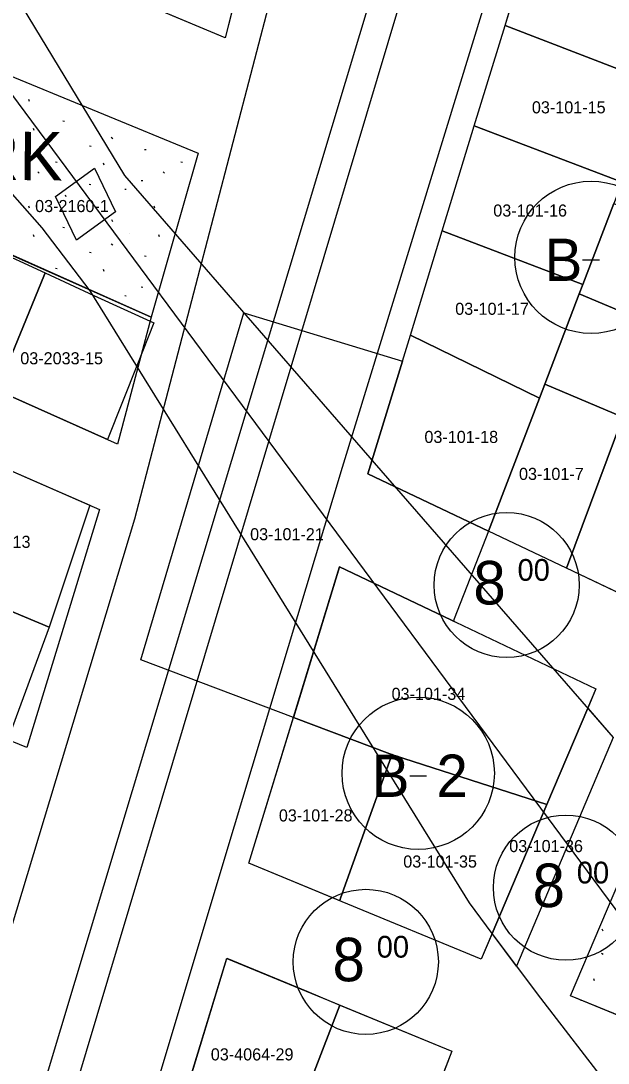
# Model space of a CAD drawing. Extents: x 413946 to 415528, y 4453939 to 4454944.
# Drawn here: x 414280.9 to 414329.5, y 4454485.6 to 4454571.8 of the extents above; entities that cross this region are included whole.
import ezdxf

# ---------------------------------------------------------------- set-up
doc = ezdxf.new("R2010")
doc.units = 0
for name, color, linetype in [('0_KADASTRO', 7, 'Continuous'), ('HAT_ENERJI_NAKIL_HAT', 7, 'Continuous'), ('KST_ENERJI_NAKIL_HAT', 7, 'Continuous'), ('Level 27', 7, 'Continuous'), ('Level 28', 7, 'Continuous'), ('Level 33', 7, 'Continuous'), ('Level 41', 7, 'Continuous'), ('Level 54', 7, 'Continuous'), ('Level 62', 7, 'Continuous'), ('SEMBOL', 7, 'Continuous'), ('SNR_FONKSIYON', 7, 'Continuous')]:
    doc.layers.add(name, color=color, linetype=linetype)

msp = doc.modelspace()

# ---------------------------------------------------------------- linework, layer by layer
at = {"layer": '0_KADASTRO'}
for points in [[(414286.69, 4454575.03), (414291.62, 4454587.04), (414300.98, 4454583.13), (414297.78, 4454570.38)], [(414320.92, 4454571.39), (414322.76, 4454577.41), (414331.26, 4454579.45), (414337.788, 4454577.207), (414333.68, 4454566.5)], [(414318.38, 4454563.09), (414320.92, 4454571.39), (414333.68, 4454566.5), (414332.781, 4454564.135), (414330.6, 4454558.43)], [(414315.73, 4454554.42), (414318.38, 4454563.09), (414330.6, 4454558.43), (414329.929, 4454556.663), (414327.36, 4454549.97)], [(414283.74, 4454557.25), (414286.97, 4454559.61), (414288.7, 4454556), (414285.46, 4454553.65)], [(414327.067, 4454549.19), (414327.36, 4454549.97), (414329.929, 4454556.663), (414343.614, 4454550.92), (414340.572, 4454543.529)], [(414269.78, 4454545.14), (414273.74, 4454555.12), (414282.87, 4454550.93), (414282.76, 4454550.67), (414278.88, 4454541.23)], [(414313.09, 4454545.79), (414315.73, 4454554.42), (414327.36, 4454549.97), (414327.067, 4454549.19), (414324.214, 4454541.717), (414323.77, 4454540.57)], [(414278.88, 4454541.23), (414282.76, 4454550.67), (414282.87, 4454550.93), (414286.91, 4454549.07), (414291.86, 4454546.81), (414290.51, 4454543.39), (414288.04, 4454537.14)], [(414324.214, 4454541.717), (414327.067, 4454549.19), (414340.572, 4454543.529), (414337.521, 4454536.129), (414330.668, 4454539.005)], [(414290.801, 4454518.931), (414299.317, 4454547.634), (414312.43, 4454543.62), (414309.58, 4454534.32), (414319.567, 4454529.572), (414316.724, 4454522.33), (414316.645, 4454522.13), (414316.45, 4454522.223), (414307.22, 4454526.61), (414303.41, 4454514.17)], [(414309.58, 4454534.32), (414312.43, 4454543.62), (414313.09, 4454545.79), (414323.77, 4454540.57), (414319.567, 4454529.572)], [(414319.567, 4454529.572), (414323.77, 4454540.57), (414324.214, 4454541.717), (414330.668, 4454539.005), (414325.997, 4454526.51)], [(414325.997, 4454526.51), (414330.668, 4454539.005), (414337.521, 4454536.129), (414332.319, 4454523.508)], [(414272.97, 4454525.89), (414277.34, 4454535.75), (414286.58, 4454531.72), (414283.2, 4454521.62)], [(414303.41, 4454514.17), (414307.22, 4454526.61), (414316.45, 4454522.223), (414316.645, 4454522.13), (414316.85, 4454522.035), (414328.44, 4454516.52), (414327.763, 4454514.924), (414324.377, 4454506.951), (414311.78, 4454511.025), (414311.579, 4454511.087), (414311.38, 4454511.162)], [(414269.13, 4454516.67), (414272.5, 4454526.06), (414272.97, 4454525.89), (414283.2, 4454521.62), (414279.78, 4454512.33)], [(414319.852, 4454496.293), (414324.377, 4454506.951), (414327.763, 4454514.924), (414329.869, 4454512.498), (414321.859, 4454493.598)], [(414299.72, 4454502.11), (414303.41, 4454514.17), (414311.38, 4454511.162), (414311.579, 4454511.087), (414311.508, 4454510.89), (414307.323, 4454499.2), (414307.251, 4454499), (414307.05, 4454499.083)], [(414307.251, 4454499), (414307.323, 4454499.2), (414311.508, 4454510.89), (414311.579, 4454511.087), (414311.78, 4454511.025), (414324.377, 4454506.951), (414319.852, 4454496.293), (414318.95, 4454494.17), (414307.45, 4454498.917)], [(414326.34, 4454491.12), (414331.365, 4454502.948), (414341.225, 4454498.918), (414336.39, 4454487.01)], [(414294.115, 4454481.779), (414297.9, 4454494.24), (414304.517, 4454491.51), (414307.266, 4454490.373), (414302.597, 4454478.26), (414300.137, 4454479.274)], [(414302.597, 4454478.26), (414307.266, 4454490.373), (414316.518, 4454486.562), (414311.839, 4454474.439)]]:
    msp.add_lwpolyline(points, close=True, dxfattribs=at)
at = {"layer": 'HAT_ENERJI_NAKIL_HAT'}
msp.add_lwpolyline([(414658.516, 4453939.478), (414647.224, 4454070.234), (413999.883, 4454943.957)], dxfattribs=at)
at = {"layer": 'KST_ENERJI_NAKIL_HAT'}
for p, q in [((414249.551, 4454624.916), (414289.431, 4454559.004)), ((414282.639, 4454554.651), (414232.696, 4454610.603)), ((414289.431, 4454559.004), (414303.877, 4454542.389)), ((414286.614, 4454549.462), (414282.639, 4454554.651)), ((414317.975, 4454498.823), (414286.614, 4454549.462)), ((414303.877, 4454542.389), (414311.751, 4454533.334)), ((414311.751, 4454533.334), (414320.609, 4454523.146)), ((414320.609, 4454523.146), (414329.869, 4454512.498)), ((414319.852, 4454496.293), (414317.975, 4454498.823)), ((414323.891, 4454490.931), (414319.852, 4454496.293)), ((414337.64, 4454473.12), (414323.891, 4454490.931))]:
    msp.add_line(p, q, dxfattribs=at)
at = {"layer": 'Level 27'}
for p, q in [((414288.869, 4454536.77), (414278.88, 4454541.23)), ((414277.34, 4454535.75), (414287.387, 4454531.368)), ((414281.361, 4454511.686), (414269.13, 4454516.67))]:
    msp.add_line(p, q, dxfattribs=at)
at = {"layer": 'Level 28'}
for p, q in [((414300.98, 4454583.13), (414297.78, 4454570.38)), ((414320.92, 4454571.39), (414322.76, 4454577.41)), ((414297.78, 4454570.38), (414286.69, 4454575.03)), ((414318.38, 4454563.09), (414320.92, 4454571.39)), ((414270.493, 4454571.163), (414295.525, 4454560.843)), ((414315.73, 4454554.42), (414318.38, 4454563.09)), ((414295.525, 4454560.843), (414291.656, 4454547.282)), ((414313.09, 4454545.79), (414315.73, 4454554.42)), ((414291.656, 4454547.282), (414288.869, 4454536.77)), ((414312.43, 4454543.62), (414313.09, 4454545.79)), ((414309.58, 4454534.32), (414312.43, 4454543.62)), ((414319.567, 4454529.572), (414309.58, 4454534.32)), ((414287.387, 4454531.368), (414281.361, 4454511.686)), ((414325.997, 4454526.51), (414319.567, 4454529.572)), ((414299.72, 4454502.11), (414307.22, 4454526.61)), ((414307.22, 4454526.61), (414316.85, 4454522.035)), ((414332.319, 4454523.508), (414325.997, 4454526.51)), ((414316.85, 4454522.035), (414328.44, 4454516.52)), ((414328.44, 4454516.52), (414324.377, 4454506.951)), ((414324.377, 4454506.951), (414318.95, 4454494.17)), ((414326.34, 4454491.12), (414331.365, 4454502.948)), ((414307.45, 4454498.917), (414299.72, 4454502.11)), ((414318.95, 4454494.17), (414307.45, 4454498.917)), ((414294.115, 4454481.779), (414297.898, 4454494.232)), ((414297.898, 4454494.232), (414316.518, 4454486.562)), ((414336.39, 4454487.01), (414326.34, 4454491.12)), ((414316.518, 4454486.562), (414311.839, 4454474.439))]:
    msp.add_line(p, q, dxfattribs=at)
at = {"layer": 'Level 41'}
for p, q in [((414281.594, 4454565.107), (414281.529, 4454565.27)), ((414281.594, 4454565.107), (414281.529, 4454565.27)), ((414284.34, 4454563.519), (414284.467, 4454563.495)), ((414284.34, 4454563.519), (414284.467, 4454563.495)), ((414281.976, 4454562.725), (414281.911, 4454562.887)), ((414281.976, 4454562.725), (414281.911, 4454562.887)), ((414289.824, 4454562.994), (414289.833, 4454562.992)), ((414289.824, 4454562.994), (414289.833, 4454562.992)), ((414288.349, 4454562.155), (414288.476, 4454562.057)), ((414288.349, 4454562.155), (414288.476, 4454562.057)), ((414286.556, 4454561.451), (414286.682, 4454561.426)), ((414286.556, 4454561.451), (414286.682, 4454561.426)), ((414291.104, 4454561.156), (414291.23, 4454561.133)), ((414291.104, 4454561.156), (414291.23, 4454561.133)), ((414283.735, 4454560.132), (414283.86, 4454560.108)), ((414283.735, 4454560.132), (414283.86, 4454560.108)), ((414287.769, 4454559.853), (414287.704, 4454560.015)), ((414287.769, 4454559.853), (414287.704, 4454560.015)), ((414294.103, 4454560.132), (414294.228, 4454560.108)), ((414294.103, 4454560.132), (414294.228, 4454560.108)), ((414282.26, 4454559.294), (414282.387, 4454559.195)), ((414282.26, 4454559.294), (414282.387, 4454559.195)), ((414292.628, 4454559.294), (414292.755, 4454559.195)), ((414292.628, 4454559.294), (414292.755, 4454559.195)), ((414286.529, 4454558.285), (414286.655, 4454558.261)), ((414286.529, 4454558.285), (414286.655, 4454558.261)), ((414290.834, 4454558.589), (414290.96, 4454558.565)), ((414290.834, 4454558.589), (414290.96, 4454558.565)), ((414289.458, 4454557.875), (414289.584, 4454557.85)), ((414289.458, 4454557.875), (414289.584, 4454557.85)), ((414284.625, 4454557.216), (414284.559, 4454557.378)), ((414284.625, 4454557.216), (414284.559, 4454557.378)), ((414281.594, 4454556.301), (414281.529, 4454556.464)), ((414281.594, 4454556.301), (414281.529, 4454556.464)), ((414285.944, 4454556.08), (414286.07, 4454556.057)), ((414285.944, 4454556.08), (414286.07, 4454556.057)), ((414291.962, 4454556.301), (414291.897, 4454556.464)), ((414291.962, 4454556.301), (414291.897, 4454556.464)), ((414288.467, 4454555.152), (414288.403, 4454555.313)), ((414288.467, 4454555.152), (414288.403, 4454555.313)), ((414281.976, 4454553.919), (414281.911, 4454554.081)), ((414281.976, 4454553.919), (414281.911, 4454554.081)), ((414284.34, 4454554.713), (414284.467, 4454554.689)), ((414284.34, 4454554.713), (414284.467, 4454554.689)), ((414289.824, 4454554.188), (414289.833, 4454554.186)), ((414289.824, 4454554.188), (414289.833, 4454554.186)), ((414292.344, 4454553.919), (414292.279, 4454554.081)), ((414292.344, 4454553.919), (414292.279, 4454554.081)), ((414288.349, 4454553.349), (414288.476, 4454553.251)), ((414288.349, 4454553.349), (414288.476, 4454553.251)), ((414286.556, 4454552.645), (414286.682, 4454552.62)), ((414286.556, 4454552.645), (414286.682, 4454552.62)), ((414291.104, 4454552.35), (414291.23, 4454552.327)), ((414291.104, 4454552.35), (414291.23, 4454552.327)), ((414283.735, 4454551.326), (414283.86, 4454551.302)), ((414283.735, 4454551.326), (414283.86, 4454551.302)), ((414287.769, 4454551.047), (414287.704, 4454551.209)), ((414287.769, 4454551.047), (414287.704, 4454551.209)), ((414290.834, 4454549.783), (414290.96, 4454549.759)), ((414290.834, 4454549.783), (414290.96, 4454549.759)), ((414289.458, 4454549.069), (414289.584, 4454549.044)), ((414289.458, 4454549.069), (414289.584, 4454549.044)), ((414329.03, 4454496.476), (414328.966, 4454496.638)), ((414329.03, 4454496.476), (414328.966, 4454496.638)), ((414328.913, 4454494.674), (414329.04, 4454494.575)), ((414328.913, 4454494.674), (414329.04, 4454494.575)), ((414328.332, 4454492.371), (414328.267, 4454492.533)), ((414328.332, 4454492.371), (414328.267, 4454492.533)), ((414327.134, 4454490.795), (414327.218, 4454490.78)), ((414327.134, 4454490.795), (414327.218, 4454490.78))]:
    msp.add_line(p, q, dxfattribs=at)
at = {"layer": 'Level 54'}
for points in [[(414197.13, 4454601.67), (414206.35, 4454597.81), (414215.57, 4454593.95), (414223.86, 4454590.48), (414232.17, 4454587.01), (414240.47, 4454583.54), (414270.493, 4454571.163), (414265.71, 4454558.81), (414291.656, 4454547.282), (414288.869, 4454536.77), (414278.88, 4454541.23), (414269.78, 4454545.14), (414193.078, 4454579.23)], [(414300.98, 4454583.13), (414297.78, 4454570.38), (414286.69, 4454575.03)], [(414195.58, 4454571.57), (414204.05, 4454567.79), (414213.18, 4454563.73), (414222.37, 4454559.64), (414231.54, 4454555.74), (414240.74, 4454551.69), (414249.78, 4454547.7), (414258.92, 4454543.67), (414268.07, 4454539.64), (414277.34, 4454535.75), (414287.387, 4454531.368), (414281.361, 4454511.686), (414269.13, 4454516.67), (414259.9, 4454520.54), (414260, 4454520.84), (414249.37, 4454525.29), (414240.24, 4454529.13), (414231.1, 4454533.09), (414221.83, 4454537.09), (414212.64, 4454541.31), (414203.51, 4454545.49), (414194.69, 4454549.53)]]:
    msp.add_lwpolyline(points, dxfattribs=at)
for points in [[(414318.38, 4454563.09), (414320.92, 4454571.39), (414322.76, 4454577.41), (414331.26, 4454579.45), (414337.788, 4454577.207), (414344.815, 4454574.789), (414352.38, 4454572.186), (414346.666, 4454558.321), (414343.614, 4454550.92), (414340.572, 4454543.529), (414337.521, 4454536.129), (414332.319, 4454523.508), (414325.997, 4454526.51), (414319.567, 4454529.572), (414309.58, 4454534.32), (414312.43, 4454543.62), (414313.09, 4454545.79), (414315.73, 4454554.42)], [(414328.44, 4454516.52), (414324.377, 4454506.951), (414318.95, 4454494.17), (414307.45, 4454498.917), (414299.72, 4454502.11), (414307.22, 4454526.61), (414316.85, 4454522.035)], [(414301.044, 4454446.448), (414295.842, 4454432.97), (414281.423, 4454439.998), (414281.423, 4454439.998), (414285.363, 4454452.967), (414288.429, 4454463.062), (414291.481, 4454473.109), (414294.115, 4454481.779), (414297.898, 4454494.232), (414297.898, 4454494.232), (414316.518, 4454486.562), (414311.839, 4454474.439), (414303.558, 4454452.982)]]:
    msp.add_lwpolyline(points, close=True, dxfattribs=at)
at = {"layer": 'Level 62'}
for points in [[(414306.536, 4454592.896), (414290.275, 4454530.555), (414274.865, 4454479.568), (414264.669, 4454435.816)], [(414268.735, 4454435.606), (414271.191, 4454445.316), (414313.658, 4454586.459), (414314.96, 4454586.615), (414315.733, 4454585.017), (414272.854, 4454441.719), (414271.147, 4454435.481)], [(414322.391, 4454583.537), (414307.444, 4454534.85), (414297.743, 4454502.599), (414279.066, 4454440.44), (414278.049, 4454435.124)]]:
    msp.add_lwpolyline(points, dxfattribs=at)
at = {"layer": 'SEMBOL'}
for p, q in [((414327.336, 4454552.016), (414328.736, 4454552.016)), ((414313.038, 4454509.337), (414314.438, 4454509.337))]:
    msp.add_line(p, q, dxfattribs=at)
for centre, radius in [((414328.036, 4454552.223), 6.3), ((414321.054, 4454525.116), 6), ((414313.738, 4454509.545), 6.3), ((414325.957, 4454500.081), 6), ((414309.405, 4454493.944), 6)]:
    msp.add_circle(centre, radius, dxfattribs=at)
at = {"layer": 'SNR_FONKSIYON'}
msp.add_line((414291.656, 4454547.282), (414265.71, 4454558.81), dxfattribs=at)

# ---------------------------------------------------------------- texts
at = {"layer": '0_KADASTRO'}
for s, p in [('03-101-15', (414323.145, 4454564.132)), ('03-2160-1', (414282.05, 4454555.966)), ('03-101-16', (414319.95, 4454555.596)), ('03-101-17', (414316.799, 4454547.467)), ('03-2033-15', (414280.821, 4454543.372)), ('03-101-18', (414314.252, 4454536.868)), ('03-101-7', (414322.077, 4454533.809)), ('03-101-21', (414299.835, 4454528.817)), ('03-2034-13', (414274.83, 4454528.19)), ('03-101-34', (414311.536, 4454515.614)), ('03-101-28', (414302.211, 4454505.56)), ('03-101-36', (414321.27, 4454503.024)), ('03-101-35', (414312.503, 4454501.743)), ('03-4064-29', (414296.582, 4454485.791))]:
    msp.add_text(s, height=1, dxfattribs=at).set_placement(p)
at = {"layer": 'Level 33'}
msp.add_text('PARK', height=4, rotation=359.4136, dxfattribs=at).set_placement((414269.737, 4454558.725))
at = {"layer": 'SEMBOL'}
for s, height, p in [('B', 3.5, (414324.192, 4454550.266)), ('00', 1.8, (414321.954, 4454525.465)), ('8', 3.6, (414318.299, 4454523.508)), ('B', 3.5, (414309.894, 4454507.587)), ('2', 3.5, (414315.246, 4454507.587)), ('00', 1.8, (414326.857, 4454500.43)), ('8', 3.6, (414323.202, 4454498.473)), ('8', 3.6, (414306.65, 4454492.336)), ('00', 1.8, (414310.305, 4454494.293))]:
    msp.add_text(s, height=height, dxfattribs=at).set_placement(p)

doc.saveas('drawing.dxf')
